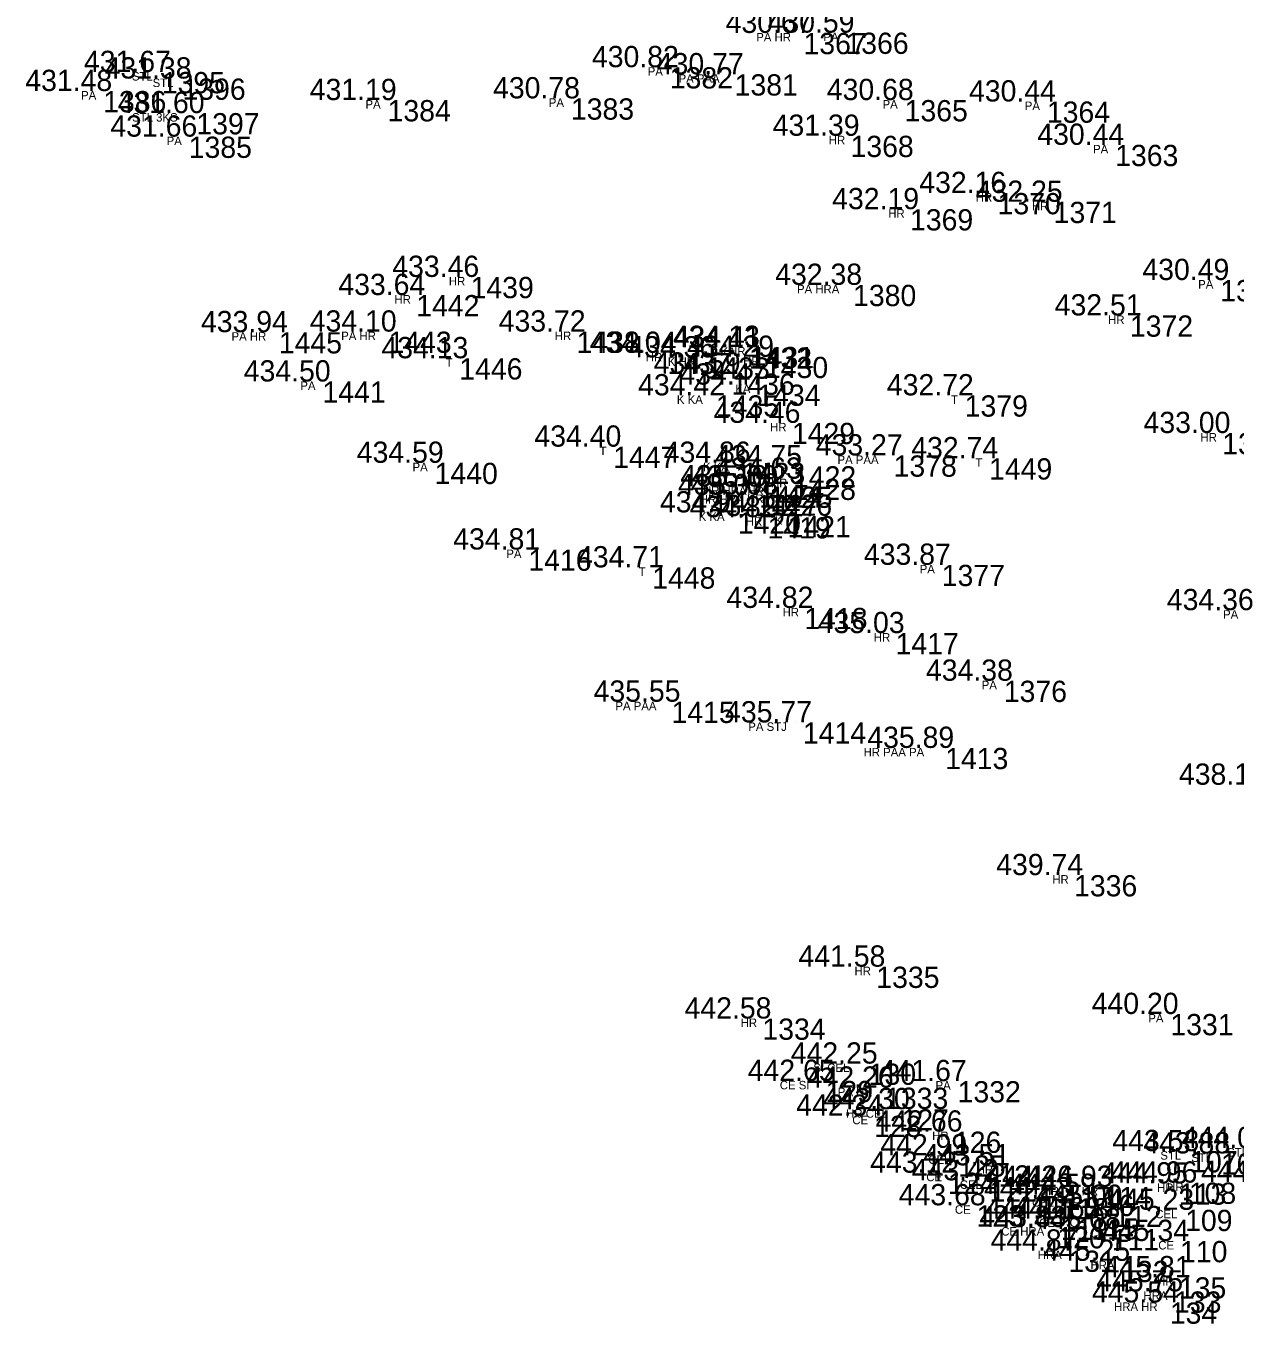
# Model space of a CAD drawing. Extents: x -639390 to -639075, y -1138747 to -1138358.
# Drawn here: x -639306.56 to -639263.88, y -1138649.43 to -1138603.62 of the extents above; entities that cross this region are included whole.
import ezdxf

# ---------------------------------------------------------------- set-up
doc = ezdxf.new("R2010")
doc.units = 0
for name, color, linetype in [('Vrstva 11', 7, 'Continuous'), ('Vrstva 12', 7, 'Continuous'), ('Vrstva 13', 7, 'Continuous'), ('Vrstva 57', 7, 'Continuous')]:
    doc.layers.add(name, color=color, linetype=linetype)

msp = doc.modelspace()

# ---------------------------------------------------------------- linework, layer by layer
at = {"layer": 'Vrstva 11'}
for p, q in [((-639279.39, -1138603.87), (-639279.39, -1138603.87)), ((-639277.91, -1138603.86), (-639277.91, -1138603.86)), ((-639284.11, -1138605.08), (-639284.11, -1138605.08)), ((-639302.04, -1138605.25), (-639302.04, -1138605.25)), ((-639301.31, -1138605.48), (-639301.31, -1138605.48)), ((-639281.82, -1138605.33), (-639281.82, -1138605.33)), ((-639304.11, -1138605.92), (-639304.11, -1138605.92)), ((-639294.07, -1138606.24), (-639294.07, -1138606.24)), ((-639287.6, -1138606.18), (-639287.6, -1138606.18)), ((-639275.82, -1138606.24), (-639275.82, -1138606.24)), ((-639270.8, -1138606.29), (-639270.8, -1138606.29)), ((-639300.82, -1138606.7), (-639300.82, -1138606.7)), ((-639301.09, -1138607.53), (-639301.09, -1138607.53)), ((-639277.73, -1138607.5), (-639277.73, -1138607.5)), ((-639268.39, -1138607.82), (-639268.39, -1138607.82)), ((-639272.54, -1138609.52), (-639272.54, -1138609.52)), ((-639275.63, -1138610.09), (-639275.63, -1138610.09)), ((-639270.56, -1138609.83), (-639270.56, -1138609.83)), ((-639291.14, -1138612.48), (-639291.14, -1138612.48)), ((-639277.64, -1138612.76), (-639277.64, -1138612.76)), ((-639264.68, -1138612.59), (-639264.68, -1138612.59)), ((-639293.06, -1138613.12), (-639293.06, -1138613.12)), ((-639267.87, -1138613.84), (-639267.87, -1138613.84)), ((-639297.91, -1138614.43), (-639297.91, -1138614.43)), ((-639294.04, -1138614.41), (-639294.04, -1138614.41)), ((-639287.4, -1138614.41), (-639287.4, -1138614.41)), ((-639284.19, -1138615.16), (-639284.19, -1138615.16)), ((-639281.32, -1138614.97), (-639281.32, -1138614.97)), ((-639281.25, -1138614.95), (-639281.25, -1138614.95)), ((-639291.54, -1138615.35), (-639291.54, -1138615.35)), ((-639282.81, -1138615.32), (-639282.81, -1138615.32)), ((-639280.75, -1138615.3), (-639280.75, -1138615.3)), ((-639281.93, -1138615.89), (-639281.93, -1138615.89)), ((-639296.37, -1138616.17), (-639296.37, -1138616.17)), ((-639281.02, -1138616.28), (-639281.02, -1138616.28)), ((-639282.48, -1138616.66), (-639282.48, -1138616.66)), ((-639273.7, -1138616.66), (-639273.7, -1138616.66)), ((-639279.8, -1138617.63), (-639279.8, -1138617.63)), ((-639264.61, -1138617.99), (-639264.61, -1138617.99)), ((-639286.11, -1138618.47), (-639286.11, -1138618.47)), ((-639276.21, -1138618.78), (-639276.21, -1138618.78)), ((-639292.41, -1138619.04), (-639292.41, -1138619.04)), ((-639281.56, -1138619.04), (-639281.56, -1138619.04)), ((-639279.76, -1138619.16), (-639279.76, -1138619.16)), ((-639272.84, -1138618.88), (-639272.84, -1138618.88)), ((-639279.77, -1138619.6), (-639279.77, -1138619.6)), ((-639281.07, -1138620.18), (-639281.07, -1138620.18)), ((-639280.96, -1138619.87), (-639280.96, -1138619.87)), ((-639280.61, -1138620.16), (-639280.61, -1138620.16)), ((-639280.6, -1138619.88), (-639280.6, -1138619.88)), ((-639281.71, -1138620.79), (-639281.71, -1138620.79)), ((-639280.66, -1138620.96), (-639280.66, -1138620.96)), ((-639279.95, -1138620.92), (-639279.95, -1138620.92)), ((-639289.1, -1138622.1), (-639289.1, -1138622.1)), ((-639284.73, -1138622.73), (-639284.73, -1138622.73)), ((-639274.51, -1138622.64), (-639274.51, -1138622.64)), ((-639279.36, -1138624.16), (-639279.36, -1138624.16)), ((-639276.14, -1138625.05), (-639276.14, -1138625.05)), ((-639272.32, -1138626.73), (-639272.32, -1138626.73)), ((-639284.05, -1138627.47), (-639284.05, -1138627.47)), ((-639279.41, -1138628.2), (-639279.41, -1138628.2)), ((-639274.39, -1138629.1), (-639274.39, -1138629.1)), ((-639269.84, -1138633.59), (-639269.84, -1138633.59)), ((-639276.82, -1138636.82), (-639276.82, -1138636.82)), ((-639266.44, -1138638.49), (-639266.44, -1138638.49)), ((-639280.84, -1138638.65), (-639280.84, -1138638.65)), ((-639277.09, -1138640.24), (-639277.09, -1138640.24)), ((-639278.61, -1138640.85), (-639278.61, -1138640.85)), ((-639276.51, -1138641.09), (-639276.51, -1138641.09)), ((-639273.95, -1138640.86), (-639273.95, -1138640.86)), ((-639276.9, -1138642.08), (-639276.9, -1138642.08)), ((-639275.93, -1138641.85), (-639275.93, -1138641.85)), ((-639274.08, -1138642.64), (-639274.08, -1138642.64)), ((-639273.93, -1138643.48), (-639273.93, -1138643.48)), ((-639265.74, -1138643.33), (-639265.74, -1138643.33)), ((-639264.65, -1138643.41), (-639264.65, -1138643.41)), ((-639272.51, -1138643.83), (-639272.51, -1138643.83)), ((-639274.29, -1138644.09), (-639274.29, -1138644.09)), ((-639272.82, -1138644.36), (-639272.82, -1138644.36)), ((-639266.14, -1138644.47), (-639266.14, -1138644.47)), ((-639265.79, -1138644.44), (-639265.79, -1138644.44)), ((-639270.18, -1138644.59), (-639270.18, -1138644.59)), ((-639269.39, -1138644.87), (-639269.39, -1138644.87)), ((-639268.8, -1138644.59), (-639268.8, -1138644.59)), ((-639273.28, -1138645.24), (-639273.28, -1138645.24)), ((-639270.27, -1138644.99), (-639270.27, -1138644.99)), ((-639268.42, -1138645.26), (-639268.42, -1138645.26)), ((-639265.92, -1138645.4), (-639265.92, -1138645.4)), ((-639270.31, -1138645.71), (-639270.31, -1138645.71)), ((-639269.23, -1138645.7), (-639269.23, -1138645.7)), ((-639270.43, -1138646.01), (-639270.43, -1138646.01)), ((-639268.51, -1138646.08), (-639268.51, -1138646.08)), ((-639266.1, -1138646.5), (-639266.1, -1138646.5)), ((-639270.04, -1138646.84), (-639270.04, -1138646.84)), ((-639268.18, -1138647.2), (-639268.18, -1138647.2)), ((-639266.14, -1138647.78), (-639266.14, -1138647.78)), ((-639266.31, -1138648.28), (-639266.31, -1138648.28)), ((-639266.46, -1138648.67), (-639266.46, -1138648.67))]:
    msp.add_line(p, q, dxfattribs=at)

# ---------------------------------------------------------------- texts
at = {"layer": 'Vrstva 12'}
for s, p in [('430.67 ', (-639281.859, -1138603.87)), ('430.59 ', (-639280.379, -1138603.86)), ('431.67 ', (-639304.509, -1138605.25)), ('430.82 ', (-639286.579, -1138605.08)), ('430.77 ', (-639284.289, -1138605.33)), ('431.38 ', (-639303.779, -1138605.48)), ('431.48 ', (-639306.579, -1138605.92)), ('431.19 ', (-639296.539, -1138606.24)), ('430.78 ', (-639290.069, -1138606.18)), ('430.68 ', (-639278.289, -1138606.24)), ('430.44 ', (-639273.269, -1138606.29)), ('431.60 ', (-639303.319, -1138606.7)), ('431.66 ', (-639303.576, -1138607.53)), ('431.39 ', (-639280.199, -1138607.5)), ('430.44 ', (-639270.859, -1138607.82)), ('432.16 ', (-639275.026, -1138609.52)), ('432.25 ', (-639273.03, -1138609.83)), ('432.19 ', (-639278.099, -1138610.09)), ('433.46 ', (-639293.626, -1138612.48)), ('430.49 ', (-639267.149, -1138612.59)), ('433.64 ', (-639295.529, -1138613.12)), ('432.38 ', (-639280.109, -1138612.76)), ('432.51 ', (-639270.245, -1138613.84)), ('433.94 ', (-639300.379, -1138614.43)), ('434.10 ', (-639296.539, -1138614.41)), ('433.72 ', (-639289.869, -1138614.41)), ('434.13 ', (-639283.719, -1138614.95)), ('434.41 ', (-639283.695, -1138614.97)), ('434.13 ', (-639294.009, -1138615.35)), ('434.04 ', (-639286.659, -1138615.16)), ('434.36 ', (-639285.296, -1138615.32)), ('434.29 ', (-639283.219, -1138615.3)), ('434.59 ', (-639284.399, -1138615.89)), ('434.50 ', (-639298.869, -1138616.17)), ('434.47 ', (-639283.489, -1138616.28)), ('434.42 ', (-639284.949, -1138616.66)), ('432.72 ', (-639276.169, -1138616.66)), ('434.46 ', (-639282.286, -1138617.63)), ('433.00 ', (-639267.109, -1138617.99)), ('434.40 ', (-639288.609, -1138618.47)), ('434.59 ', (-639294.879, -1138619.04)), ('434.86 ', (-639284.046, -1138619.04)), ('434.75 ', (-639282.23, -1138619.16)), ('433.27 ', (-639278.679, -1138618.78)), ('432.74 ', (-639275.309, -1138618.88)), ('434.63 ', (-639282.239, -1138619.6)), ('435.10 ', (-639283.459, -1138619.87)), ('435.09 ', (-639283.069, -1138619.88)), ('435.07 ', (-639283.539, -1138620.18)), ('435.08 ', (-639283.079, -1138620.16)), ('434.94 ', (-639284.179, -1138620.79)), ('434.82 ', (-639283.129, -1138620.96)), ('434.92 ', (-639282.419, -1138620.92)), ('434.81 ', (-639291.475, -1138622.1)), ('434.71 ', (-639287.105, -1138622.73)), ('433.87 ', (-639276.979, -1138622.64)), ('434.82 ', (-639281.829, -1138624.16)), ('434.36 ', (-639266.286, -1138624.24)), ('435.03 ', (-639278.609, -1138625.05)), ('434.38 ', (-639274.789, -1138626.73)), ('435.55 ', (-639286.52, -1138627.47)), ('435.77 ', (-639281.879, -1138628.2)), ('435.89 ', (-639276.859, -1138629.1)), ('438.15 ', (-639265.86, -1138630.4)), ('439.74 ', (-639272.309, -1138633.59)), ('441.58 ', (-639279.289, -1138636.82)), ('442.58 ', (-639283.309, -1138638.65)), ('440.20 ', (-639268.939, -1138638.49)), ('442.25 ', (-639279.56, -1138640.24)), ('442.65 ', (-639281.08, -1138640.85)), ('442.26 ', (-639278.996, -1138641.09)), ('441.67 ', (-639276.419, -1138640.86)), ('442.30 ', (-639278.429, -1138641.85)), ('442.34 ', (-639279.369, -1138642.08)), ('442.66 ', (-639276.566, -1138642.64)), ('443.53 ', (-639268.209, -1138643.33)), ('443.88 ', (-639267.119, -1138643.41)), ('444.01 ', (-639265.755, -1138643.22)), ('442.99 ', (-639276.399, -1138643.48)), ('443.51 ', (-639274.885, -1138643.83)), ('443.12 ', (-639276.759, -1138644.09)), ('443.42 ', (-639275.289, -1138644.36)), ('444.26 ', (-639272.666, -1138644.59)), ('444.93 ', (-639271.269, -1138644.59)), ('444.95 ', (-639268.61, -1138644.47)), ('444.96 ', (-639268.276, -1138644.44)), ('444.84 ', (-639265.079, -1138644.42)), ('443.68 ', (-639275.749, -1138645.24)), ('444.23 ', (-639272.739, -1138644.99)), ('444.59 ', (-639271.859, -1138644.87)), ('445.00 ', (-639270.919, -1138645.26)), ('444.11 ', (-639272.685, -1138645.71)), ('444.63 ', (-639271.699, -1138645.7)), ('445.23 ', (-639268.389, -1138645.4)), ('443.83 ', (-639272.899, -1138646.01)), ('445.08 ', (-639270.979, -1138646.08)), ('445.34 ', (-639268.569, -1138646.5)), ('444.87 ', (-639272.509, -1138646.84)), ('445.25 ', (-639270.65, -1138647.2)), ('445.81 ', (-639268.515, -1138647.78)), ('445.75 ', (-639268.78, -1138648.28)), ('445.54 ', (-639268.929, -1138648.67))]:
    msp.add_text(s, height=0.75, dxfattribs=at).set_placement(p)
at = {"layer": 'Vrstva 13'}
for s, p in [(' 1367', (-639279.39, -1138604.62)), (' 1366', (-639277.91, -1138604.61)), (' 1382', (-639284.11, -1138605.83)), (' 1395', (-639302.04, -1138606)), (' 1396', (-639301.31, -1138606.23)), (' 1381', (-639281.82, -1138606.08)), (' 1386', (-639304.11, -1138606.67)), (' 1384', (-639294.07, -1138606.99)), (' 1383', (-639287.6, -1138606.93)), (' 1365', (-639275.82, -1138606.99)), (' 1364', (-639270.8, -1138607.04)), (' 1397', (-639300.82, -1138607.45)), (' 1385', (-639301.09, -1138608.28)), (' 1368', (-639277.73, -1138608.25)), (' 1363', (-639268.39, -1138608.57)), (' 1370', (-639272.54, -1138610.27)), (' 1369', (-639275.63, -1138610.84)), (' 1371', (-639270.56, -1138610.58)), (' 1439', (-639291.14, -1138613.23)), (' 1380', (-639277.64, -1138613.51)), (' 1362', (-639264.68, -1138613.34)), (' 1442', (-639293.06, -1138613.87)), (' 1372', (-639267.87, -1138614.59)), (' 1445', (-639297.91, -1138615.18)), (' 1443', (-639294.04, -1138615.16)), (' 1438', (-639287.4, -1138615.16)), (' 1437', (-639284.19, -1138615.91)), (' 1432', (-639281.32, -1138615.72)), (' 1431', (-639281.25, -1138615.7)), (' 1446', (-639291.54, -1138616.1)), (' 1433', (-639282.81, -1138616.07)), (' 1430', (-639280.75, -1138616.05)), (' 1436', (-639281.93, -1138616.64)), (' 1441', (-639296.37, -1138616.92)), (' 1434', (-639281.02, -1138617.03)), (' 1435', (-639282.48, -1138617.41)), (' 1379', (-639273.7, -1138617.41)), (' 1429', (-639279.8, -1138618.38)), (' 1373', (-639264.61, -1138618.74)), (' 1447', (-639286.11, -1138619.22)), (' 1378', (-639276.21, -1138619.53)), (' 1440', (-639292.41, -1138619.79)), (' 1423', (-639281.56, -1138619.79)), (' 1422', (-639279.76, -1138619.91)), (' 1449', (-639272.84, -1138619.63)), (' 1428', (-639279.77, -1138620.35)), (' 1427', (-639281.07, -1138620.93)), (' 1424', (-639280.96, -1138620.62)), (' 1426', (-639280.61, -1138620.91)), (' 1425', (-639280.6, -1138620.63)), (' 1420', (-639281.71, -1138621.54)), (' 1419', (-639280.66, -1138621.71)), (' 1421', (-639279.95, -1138621.67)), (' 1416', (-639289.1, -1138622.85)), (' 1448', (-639284.73, -1138623.48)), (' 1377', (-639274.51, -1138623.39)), (' 1418', (-639279.36, -1138624.91)), (' 1417', (-639276.14, -1138625.8)), (' 1376', (-639272.32, -1138627.48)), (' 1415', (-639284.05, -1138628.22)), (' 1414', (-639279.41, -1138628.95)), (' 1413', (-639274.39, -1138629.85)), (' 1336', (-639269.84, -1138634.34)), (' 1335', (-639276.82, -1138637.57)), (' 1331', (-639266.44, -1138639.24)), (' 1334', (-639280.84, -1138639.4)), (' 130', (-639277.09, -1138640.99)), (' 129', (-639278.61, -1138641.6)), (' 1332', (-639273.95, -1138641.61)), (' 1333', (-639276.51, -1138641.84)), (' 128', (-639276.9, -1138642.83)), (' 127', (-639275.93, -1138642.6)), (' 126', (-639274.08, -1138643.39)), (' 125', (-639273.93, -1138644.23)), (' 107', (-639265.74, -1138644.08)), (' 106', (-639264.65, -1138644.16)), (' 121', (-639272.51, -1138644.58)), (' 124', (-639274.29, -1138644.84)), (' 122', (-639272.82, -1138645.11)), (' 113', (-639266.14, -1138645.22)), (' 108', (-639265.79, -1138645.19)), (' 117', (-639270.18, -1138645.34)), (' 116', (-639269.39, -1138645.62)), (' 114', (-639268.8, -1138645.34)), (' 123', (-639273.28, -1138645.99)), (' 118', (-639270.27, -1138645.74)), (' 112', (-639268.42, -1138646.01)), (' 109', (-639265.92, -1138646.15)), (' 119', (-639270.31, -1138646.46)), (' 115', (-639269.23, -1138646.45)), (' 120', (-639270.43, -1138646.76)), (' 111', (-639268.51, -1138646.83)), (' 110', (-639266.1, -1138647.25)), (' 131', (-639270.04, -1138647.59)), (' 132', (-639268.18, -1138647.95)), (' 135', (-639266.14, -1138648.53)), (' 133', (-639266.31, -1138649.03)), (' 134', (-639266.46, -1138649.42))]:
    msp.add_text(s, height=0.75, dxfattribs=at).set_placement(p)
at = {"layer": 'Vrstva 57'}
for s, p in [('PA HR', (-639280.779, -1138604.17)), ('PA', (-639278.41, -1138604.16)), ('PA', (-639284.61, -1138605.38)), ('STL', (-639302.815, -1138605.55)), ('STL', (-639302.085, -1138605.78)), ('PA PAA', (-639283.52, -1138605.63)), ('PA', (-639304.61, -1138606.22)), ('PA', (-639294.57, -1138606.54)), ('PA', (-639288.1, -1138606.48)), ('PA', (-639276.32, -1138606.54)), ('PA', (-639271.3, -1138606.59)), ('STL 3KS', (-639302.809, -1138607)), ('PA', (-639301.59, -1138607.83)), ('HR', (-639278.219, -1138607.8)), ('PA', (-639268.89, -1138608.12)), ('HR', (-639273.029, -1138609.82)), ('HR', (-639276.119, -1138610.39)), ('HR', (-639271.049, -1138610.13)), ('HR', (-639291.629, -1138612.78)), ('PA HRA', (-639279.34, -1138613.06)), ('PA', (-639265.18, -1138612.89)), ('HR', (-639293.549, -1138613.42)), ('HR', (-639268.359, -1138614.14)), ('PA HR', (-639299.299, -1138614.73)), ('PA HR', (-639295.429, -1138614.71)), ('HR', (-639287.889, -1138614.71)), ('HR', (-639284.679, -1138615.46)), ('K KA', (-639282.42, -1138615.27)), ('HR', (-639281.739, -1138615.25)), ('T', (-639291.74, -1138615.65)), ('K HR', (-639283.899, -1138615.62)), ('HR', (-639281.239, -1138615.6)), ('T', (-639282.13, -1138616.19)), ('PA', (-639296.87, -1138616.47)), ('KA', (-639281.52, -1138616.58)), ('K KA', (-639283.58, -1138616.96)), ('T', (-639273.9, -1138616.96)), ('HR', (-639280.289, -1138617.93)), ('HR', (-639265.099, -1138618.29)), ('T', (-639286.31, -1138618.77)), ('PA PAA', (-639277.91, -1138619.08)), ('PA', (-639292.91, -1138619.34)), ('K KA', (-639282.66, -1138619.34)), ('K', (-639279.935, -1138619.46)), ('T', (-639273.04, -1138619.18)), ('HR', (-639280.259, -1138619.9)), ('HR HRA', (-639282.77, -1138620.48)), ('HR HRA', (-639282.66, -1138620.17)), ('HR', (-639281.099, -1138620.46)), ('HR', (-639281.089, -1138620.18)), ('K KA', (-639282.81, -1138621.09)), ('HR', (-639281.149, -1138621.26)), ('K', (-639280.125, -1138621.22)), ('PA', (-639289.6, -1138622.4)), ('T', (-639284.93, -1138623.03)), ('PA', (-639275.01, -1138622.94)), ('HR', (-639279.849, -1138624.46)), ('PA', (-639264.3, -1138624.54)), ('HR', (-639276.629, -1138625.35)), ('PA', (-639272.82, -1138627.03)), ('PA PAA', (-639285.75, -1138627.77)), ('PA STJ', (-639281.06, -1138628.5)), ('HR PAA PA', (-639276.99, -1138629.4)), ('HR', (-639270.329, -1138633.89)), ('HR', (-639277.309, -1138637.12)), ('PA', (-639266.94, -1138638.79)), ('HR', (-639281.329, -1138638.95)), ('SI CEL', (-639278.765, -1138640.54)), ('CE SI', (-639279.948, -1138641.15)), ('PA HR', (-639277.899, -1138641.39)), ('PA', (-639274.45, -1138641.16)), ('HR CEL', (-639277.605, -1138642.15)), ('CE', (-639277.388, -1138642.38)), ('HR', (-639274.569, -1138642.94)), ('CEL', (-639274.705, -1138643.78)), ('STL', (-639266.515, -1138643.63)), ('STL', (-639265.425, -1138643.71)), ('STL', (-639264.155, -1138643.52)), ('HR', (-639272.999, -1138644.13)), ('CE', (-639274.777, -1138644.39)), ('CEL', (-639273.595, -1138644.66)), ('HR', (-639266.629, -1138644.77)), ('HR', (-639266.279, -1138644.74)), ('HR', (-639270.669, -1138644.89)), ('CEL', (-639270.165, -1138645.17)), ('HR', (-639269.289, -1138644.89)), ('CE', (-639273.767, -1138645.54)), ('CEL', (-639271.045, -1138645.29)), ('CEL', (-639269.195, -1138645.56)), ('CEL', (-639266.695, -1138645.7)), ('CE', (-639270.797, -1138646.01)), ('CE', (-639269.718, -1138646)), ('CE HRA', (-639272.13, -1138646.31)), ('CE', (-639268.998, -1138646.38)), ('CE', (-639266.588, -1138646.8)), ('HRA', (-639270.84, -1138647.14)), ('HRA', (-639268.98, -1138647.5)), ('HR', (-639266.629, -1138648.08)), ('HRA', (-639267.11, -1138648.58)), ('HRA HR', (-639268.149, -1138648.97))]:
    msp.add_text(s, height=0.3, dxfattribs=at).set_placement(p)

doc.saveas('drawing.dxf')
